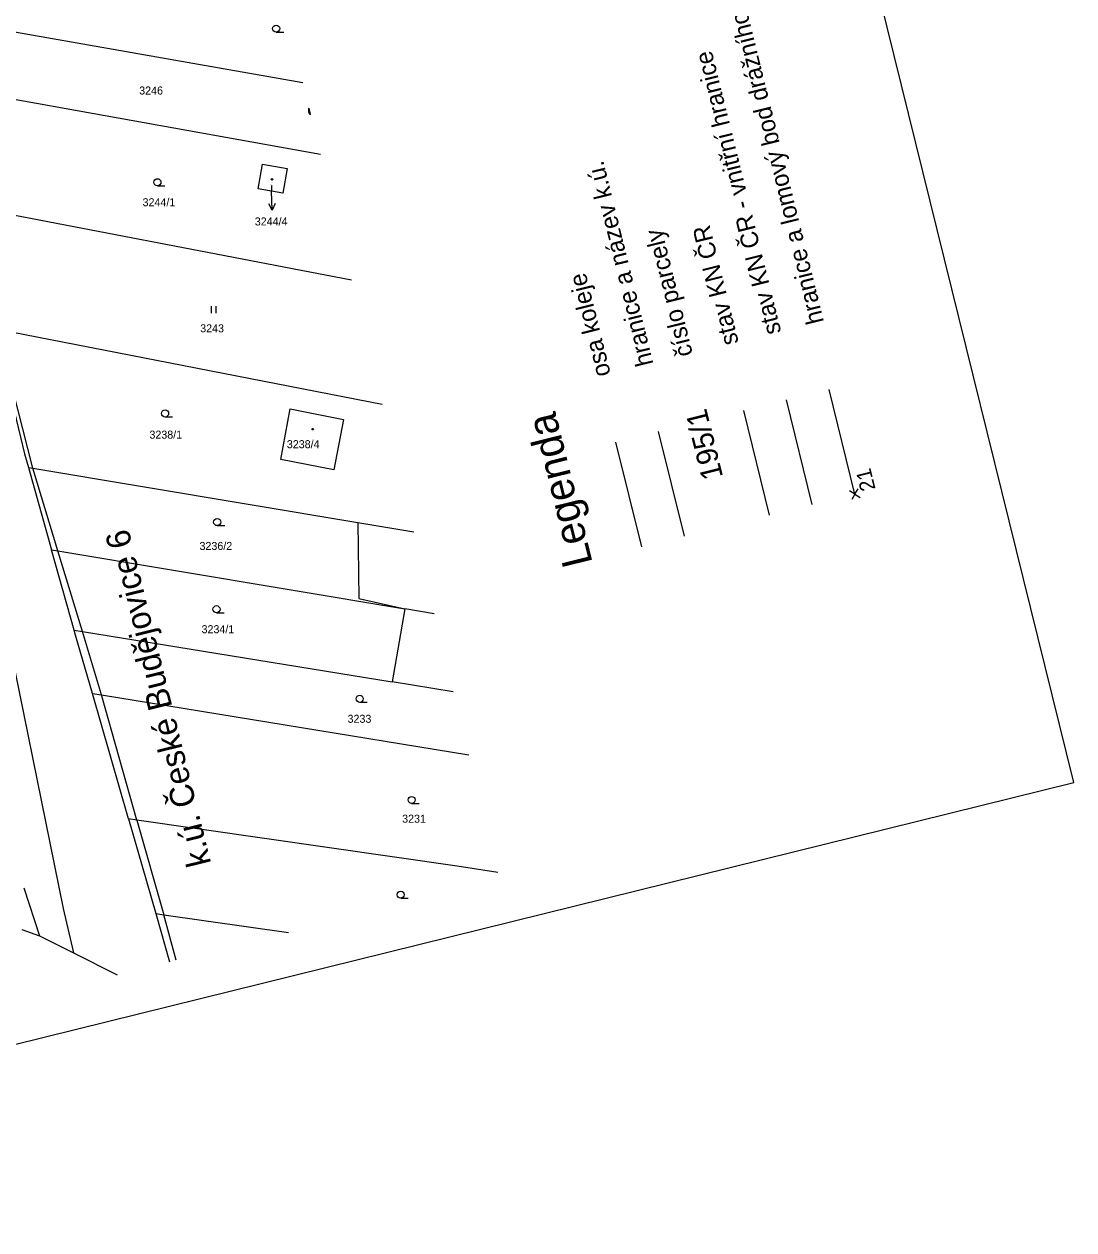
# Model space of a CAD drawing. Extents: x -754679 to -754173, y -1169241 to -1168288.
# Drawn here: x -754340.2 to -754172.8, y -1169240.8 to -1169048.7 of the extents above; entities that cross this region are included whole.
import ezdxf

# ---------------------------------------------------------------- set-up
doc = ezdxf.new("R2010")
doc.units = 0
for name, color, linetype in [('Vrstva 1', 7, 'Continuous'), ('Vrstva 13', 7, 'Continuous'), ('Vrstva 16', 7, 'Continuous'), ('Vrstva 18', 7, 'Continuous'), ('Vrstva 19', 7, 'Continuous'), ('Vrstva 24', 7, 'Continuous'), ('Vrstva 25', 7, 'Continuous'), ('Vrstva 27', 7, 'Continuous'), ('Vrstva 4', 7, 'Continuous'), ('Vrstva 61', 7, 'Continuous')]:
    doc.layers.add(name, color=color, linetype=linetype)

msp = doc.modelspace()

# ---------------------------------------------------------------- linework, layer by layer
at = {"layer": 'Vrstva 1'}
for p, q in [((-754295.74, -1169058.05), (-754356.33, -1169047.39)), ((-754292.92, -1169069.45), (-754353.72, -1169058.53)), ((-754302.84, -1169074.92), (-754302.14, -1169070.99)), ((-754302.14, -1169070.99), (-754298.2, -1169071.69)), ((-754298.2, -1169071.69), (-754298.9, -1169075.62)), ((-754298.9, -1169075.62), (-754302.84, -1169074.92)), ((-754287.96, -1169089.49), (-754348.95, -1169077.77)), ((-754344.93, -1169097.16), (-754340.1, -1169117.15)), ((-754344.43, -1169097.26), (-754283.09, -1169109.21)), ((-754299.24, -1169118.05), (-754297.74, -1169109.99)), ((-754297.74, -1169109.99), (-754289.24, -1169111.66)), ((-754289.24, -1169111.66), (-754290.78, -1169119.71)), ((-754340.1, -1169117.15), (-754339.48, -1169119.33)), ((-754339.48, -1169119.33), (-754335.79, -1169132.42)), ((-754339.48, -1169119.33), (-754338.76, -1169119.45)), ((-754338.76, -1169119.45), (-754286.94, -1169128.09)), ((-754290.78, -1169119.71), (-754299.24, -1169118.05)), ((-754286.94, -1169128.09), (-754286.82, -1169140.21)), ((-754286.94, -1169128.09), (-754278.05, -1169129.57)), ((-754345.91, -1169130.8), (-754333.91, -1169189.61)), ((-754332.18, -1169145.23), (-754335.79, -1169132.42)), ((-754335.79, -1169132.42), (-754334.76, -1169132.59)), ((-754334.76, -1169132.59), (-754279.48, -1169141.86)), ((-754286.82, -1169140.21), (-754279.48, -1169141.86)), ((-754279.48, -1169141.86), (-754281.48, -1169153.48)), ((-754274.82, -1169142.64), (-754279.48, -1169141.86)), ((-754331.95, -1169146.03), (-754332.18, -1169145.23)), ((-754332.18, -1169145.23), (-754330.83, -1169145.45)), ((-754329.28, -1169155.32), (-754331.95, -1169146.03)), ((-754330.83, -1169145.45), (-754281.48, -1169153.48)), ((-754271.75, -1169155.06), (-754281.48, -1169153.48)), ((-754323.52, -1169175.33), (-754329.28, -1169155.32)), ((-754329.28, -1169155.32), (-754327.8, -1169155.56)), ((-754327.8, -1169155.56), (-754269.27, -1169165.09)), ((-754322.18, -1169175.52), (-754323.52, -1169175.33)), ((-754323.52, -1169175.33), (-754319.18, -1169190.4)), ((-754271.14, -1169182.86), (-754322.18, -1169175.52)), ((-754264.63, -1169183.84), (-754271.14, -1169182.86)), ((-754340.21, -1169186.28), (-754337.71, -1169193.96)), ((-754333.91, -1169189.61), (-754332.3, -1169196.67)), ((-754319.18, -1169190.4), (-754317.87, -1169190.59)), ((-754319.18, -1169190.4), (-754316.97, -1169198.1)), ((-754317.87, -1169190.59), (-754298.04, -1169193.42))]:
    msp.add_line(p, q, dxfattribs=at)
at = {"layer": 'Vrstva 13'}
for p, q in [((-754340.53, -1169192.94), (-754337.71, -1169193.96)), ((-754337.71, -1169193.96), (-754332.3, -1169196.67)), ((-754332.3, -1169196.67), (-754325.31, -1169200.16))]:
    msp.add_line(p, q, dxfattribs=at)
at = {"layer": 'Vrstva 16'}
for p in [(-754300.73, -1169074.38), (-754300.61, -1169078.31)]:
    msp.add_line(p, (-754300.7, -1169075.31), dxfattribs=at)
msp.add_lwpolyline([(-754300.14, -1169077.29), (-754300.61, -1169078.31), (-754301.14, -1169077.32)], dxfattribs=at)
at = {"layer": 'Vrstva 24'}
msp.add_line((-754234.92, -1169130.27), (-754239.04, -1169113.6), dxfattribs=at)
at = {"layer": 'Vrstva 25'}
for p, q in [((-754299.98, -1169049.96), (-754298.78, -1169049.96)), ((-754294.49, -1169063.1), (-754294.74, -1169062.07)), ((-754318.9, -1169074.43), (-754317.7, -1169074.43)), ((-754310.31, -1169094.73), (-754310.31, -1169093.6)), ((-754309.56, -1169094.73), (-754309.56, -1169093.6)), ((-754317.68, -1169111.28), (-754316.48, -1169111.28)), ((-754309.38, -1169128.59), (-754308.18, -1169128.59)), ((-754309.49, -1169142.46), (-754308.29, -1169142.46)), ((-754286.66, -1169156.74), (-754285.46, -1169156.74)), ((-754278.39, -1169172.85), (-754277.19, -1169172.85)), ((-754280.13, -1169187.95), (-754278.93, -1169187.95))]:
    msp.add_line(p, q, dxfattribs=at)
for centre, radius in [((-754299.98, -1169049.4), 0.562), ((-754318.9, -1169073.87), 0.562), ((-754300.63, -1169073.41), 0.131), ((-754317.68, -1169110.72), 0.562), ((-754294.16, -1169113.22), 0.131), ((-754309.38, -1169128.03), 0.562), ((-754309.49, -1169141.9), 0.562), ((-754286.66, -1169156.18), 0.562), ((-754278.39, -1169172.29), 0.562), ((-754280.13, -1169187.39), 0.562)]:
    msp.add_circle(centre, radius, dxfattribs=at)
msp.add_arc((-754294.1, -1169062.46), 0.75, 148.7825, 238.9966, dxfattribs=at)
at = {"layer": 'Vrstva 27'}
for p, q in [((-754207.74, -1169123.56), (-754211.86, -1169106.88)), ((-754214.53, -1169125.24), (-754218.66, -1169108.56)), ((-754221.33, -1169126.92), (-754225.45, -1169110.24)), ((-754241.72, -1169131.95), (-754245.84, -1169115.27)), ((-754207.74, -1169123.56), (-754208.59, -1169123.04)), ((-754207.74, -1169123.56), (-754207.22, -1169122.7)), ((-754207.74, -1169123.56), (-754208.25, -1169124.42)), ((-754207.74, -1169123.56), (-754206.88, -1169124.08))]:
    msp.add_line(p, q, dxfattribs=at)
at = {"layer": 'Vrstva 4'}
for p, q in [((-754338.76, -1169119.45), (-754344.43, -1169097.26)), ((-754334.76, -1169132.59), (-754338.76, -1169119.45)), ((-754330.83, -1169145.45), (-754334.76, -1169132.59)), ((-754327.8, -1169155.56), (-754330.83, -1169145.45)), ((-754322.18, -1169175.52), (-754327.8, -1169155.56)), ((-754322.18, -1169175.52), (-754317.87, -1169190.59)), ((-754315.9, -1169197.83), (-754317.87, -1169190.59))]:
    msp.add_line(p, q, dxfattribs=at)
at = {"layer": 'Vrstva 61'}
msp.add_lwpolyline([(-754461.15, -1169240.8), (-754172.83, -1169169.5), (-754273.65, -1168761.78), (-754561.97, -1168833.08)], dxfattribs=at)

# ---------------------------------------------------------------- texts
at = {"layer": 'Vrstva 16'}
msp.add_text('3244/4', height=1.275, rotation=360, dxfattribs=at).set_placement((-754303.39, -1169080.76))
at = {"layer": 'Vrstva 18'}
for s, p in [('3246', (-754321.81, -1169059.9)), ('3244/1', (-754321.27, -1169077.7)), ('3243', (-754312.09, -1169097.79)), ('3238/1', (-754320.18, -1169114.73)), ('3236/2', (-754312.2, -1169132.46)), ('3234/1', (-754311.87, -1169145.73)), ('3233', (-754288.6, -1169160)), ('3231', (-754279.9, -1169175.92))]:
    msp.add_text(s, height=1.275, rotation=360, dxfattribs=at).set_placement(p)
at = {"layer": 'Vrstva 19'}
msp.add_text('3244/4', height=0.1, dxfattribs=at).set_placement((-754300.98, -1169074.38))
msp.add_text('3238/4', height=1.275, rotation=360, dxfattribs=at).set_placement((-754298.28, -1169116.25))
at = {"layer": 'Vrstva 24'}
msp.add_text('k.ú. České Budějovice 6', height=3.84, rotation=103.8896, dxfattribs=at).set_placement((-754310.33, -1169182.41))
at = {"layer": 'Vrstva 27'}
for s, height, rotation, p in [('hranice a lomový bod drážního pozemku', 2.8, 103.8896, (-754212.65, -1169096.12)), ('stav KN ČR - vnitřní hranice', 2.8, 103.8896, (-754219.45, -1169097.79)), ('hranice a název k.ú.', 2.8, 103.8896, (-754239.83, -1169102.82)), ('stav KN ČR', 2.8, 103.8896, (-754226.24, -1169099.47)), ('číslo parcely', 2.8, 103.8896, (-754233.54, -1169101.32)), ('osa koleje', 2.8, 103.8896, (-754246.63, -1169104.5)), ('Legenda', 4.8, 103.9106, (-754249.51, -1169134.52)), ('195/1', 3.4, 103.8896, (-754228.73, -1169120.82)), ('21', 2.4, 103.8686, (-754204.43, -1169122.75))]:
    msp.add_text(s, height=height, rotation=rotation, dxfattribs=at).set_placement(p)

doc.saveas('drawing.dxf')
